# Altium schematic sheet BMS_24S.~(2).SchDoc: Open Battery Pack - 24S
size A3; Date: 26/03/2019; Author: Morgane Vallée - Samuel Lesueur; Revision: 1.0; SheetNumber: 1; SheetTotal: 2
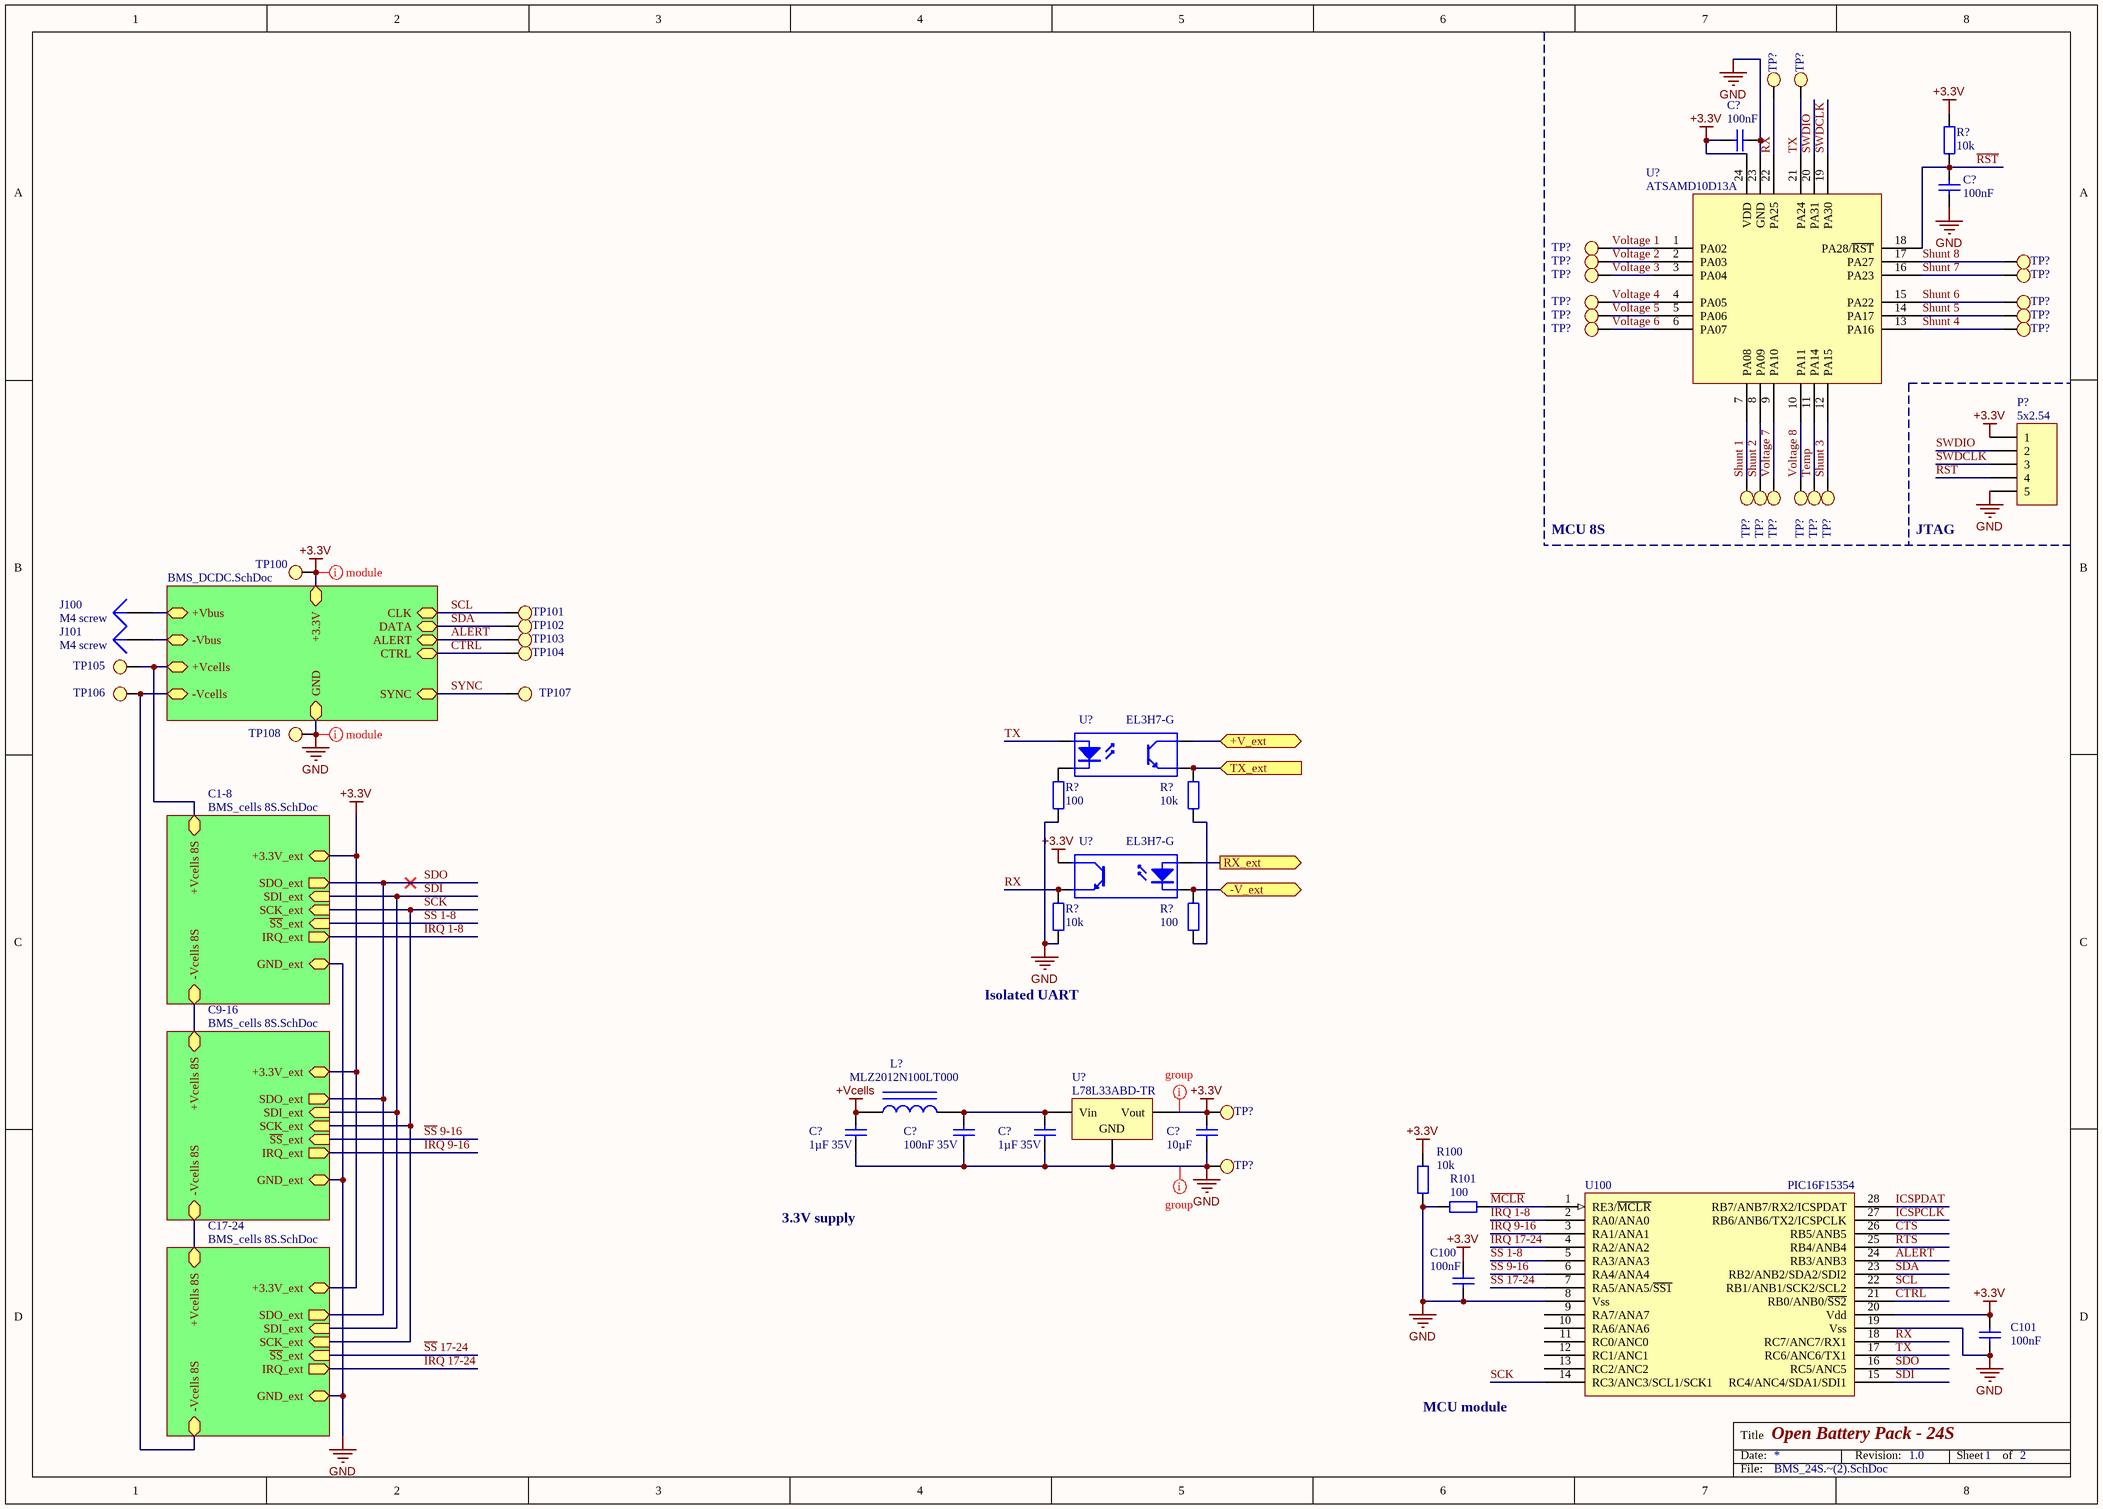
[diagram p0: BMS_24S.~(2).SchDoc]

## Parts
(Parts that share a designator on the sheet are numbered #1, #2 ... from top to bottom, then left to right.)
C100  100nF  [C0603]
C101  100nF  [C0603]
C?#1  100nF  [C0603]
C?#2  100nF  [C0603]
C?#3  1µF 35V  [C0805]
C?#4  100nF 35V  [C0603]
C?#5  1µF 35V  [C0805]
C?#6  10µF  [C0603]
J100  M4 screw  [HOLE_4]
J101  M4 screw  [HOLE_4]
L?  MLZ2012N100LT000  [FER 0805/2012]
P?  5x2.54  [HDR1X5]
R100  10k  [R0603]
R101  100  [R0603]
R?#1  10k  [R0603]
R?#2  10k  [R0603]
R?#3  100  [R0603]
R?#4  100  [R0603]
R?#5  10k  [R0603]
TP100  Test Point  [Test Point]  (value not drawn)
TP101  Test Point  [Test Point]  (value not drawn)
TP102  Test Point  [Test Point]  (value not drawn)
TP103  Test Point  [Test Point]  (value not drawn)
TP104  Test Point  [Test Point]  (value not drawn)
TP105  Test Point  [Test Point]  (value not drawn)
TP106  Test Point  [Test Point]  (value not drawn)
TP107  Test Point  [Test Point]  (value not drawn)
TP108  Test Point  [Test Point]  (value not drawn)
TP?#1  Test Point  [Test Point]  (value not drawn)
TP?#2  Test Point  [Test Point]  (value not drawn)
TP?#3  Test Point  [Test Point]  (value not drawn)
TP?#4  Test Point  [Test Point]  (value not drawn)
TP?#5  Test Point  [Test Point]  (value not drawn)
TP?#6  Test Point  [Test Point]  (value not drawn)
TP?#7  Test Point  [Test Point]  (value not drawn)
TP?#8  Test Point  [Test Point]  (value not drawn)
TP?#9  Test Point  [Test Point]  (value not drawn)
TP?#10  Test Point  [Test Point]  (value not drawn)
TP?#11  Test Point  [Test Point]  (value not drawn)
TP?#12  Test Point  [Test Point]  (value not drawn)
TP?#13  Test Point  [Test Point]  (value not drawn)
TP?#14  Test Point  [Test Point]  (value not drawn)
TP?#15  Test Point  [Test Point]  (value not drawn)
TP?#16  Test Point  [Test Point]  (value not drawn)
TP?#17  Test Point  [Test Point]  (value not drawn)
TP?#18  Test Point  [Test Point]  (value not drawn)
TP?#19  Test Point  [Test Point]  (value not drawn)
TP?#20  Test Point  [Test Point]  (value not drawn)
TP?#21  Test Point  [Test Point]  (value not drawn)
U100  PIC16F15354  [SSOP_28]
U?#1  ATSAMD10D13A  [SMSC QFN-24 4x4MM]
U?#2  EL3H7-G  [OPTO_EL3H7-G]
U?#3  EL3H7-G  [OPTO_EL3H7-G]
U?#4  L78L33ABD-TR  [ST SOIC-8N]

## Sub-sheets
C1-8 = BMS_cells 8S.SchDoc: ~{SS}_ext (in), GND_ext, +3.3V_ext, SCK_ext (in), SDO_ext (out), SDI_ext (in), IRQ_ext (out), -Vcells 8S, +Vcells 8S
C9-16 = BMS_cells 8S.SchDoc: ~{SS}_ext (in), GND_ext, +3.3V_ext, SCK_ext (in), SDO_ext (out), SDI_ext (in), IRQ_ext (out), -Vcells 8S, +Vcells 8S
C17-24 = BMS_cells 8S.SchDoc: ~{SS}_ext (in), GND_ext, +3.3V_ext, SCK_ext (in), SDO_ext (out), SDI_ext (in), IRQ_ext (out), -Vcells 8S, +Vcells 8S
? = BMS_DCDC.SchDoc: CTRL (bidir), SYNC (bidir), CLK (bidir), DATA (bidir), ALERT (bidir), GND, +3.3V, -Vbus, +Vbus, -Vcells, +Vcells

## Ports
+V_ext, -V_ext, RX_ext (out), TX_ext (in)

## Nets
+3.3V: C100.2 C101.2 C?#1.2 C?#6.1 P?.1 R100.2 R?#1.2 TP100.1 TP?#20.1 U100.20(Vdd) U?#1.24(VDD) U?#3.4(C) U?#4.3(Vout) ; sheet /+3.3V, sheet C1-8/+3.3V_ext, sheet C9-16/+3.3V_ext, sheet C17-24/+3.3V_ext
+Vcells: C?#3.1 L?.1
GND: C100.1 C101.1 C?#1.1 C?#2.1 C?#3.2 C?#4.2 C?#5.2 C?#6.2 P?.5 R100.1 R101.2 R?#3.1 R?#5.1 TP108.1 TP?#21.1 U100.8(Vss) U100.19(Vss) U?#1.23(GND) U?#4.2(GND) ; sheet /GND, sheet C1-8/GND_ext, sheet C9-16/GND_ext, sheet C17-24/GND_ext
+V_ext: U?#2.4(C) ; port +V_ext
-V_ext: R?#4.1 U?#3.2(K) ; port -V_ext
ALERT: TP103.1 U100.24(RB3/ANB3) ; sheet /ALERT
CTRL: TP104.1 U100.21(RB0/ANB0/~{SS2}) ; sheet /CTRL
CTS: U100.26(RB5/ANB5)
ICSPCLK: U100.27(RB6/ANB6/TX2/ICSPCLK)
ICSPDAT: U100.28(RB7/ANB7/RX2/ICSPDAT)
IRQ 1-8: U100.2(RA0/ANA0) ; sheet C1-8/IRQ_ext
IRQ 9-16: U100.3(RA1/ANA1) ; sheet C9-16/IRQ_ext
IRQ 17-24: U100.4(RA2/ANA2) ; sheet C17-24/IRQ_ext
~{MCLR}: R101.1 U100.1(RE3/~{MCLR})
~{RST}: C?#2.2 P?.4 R?#1.1 U?#1.18(PA28/~{RST})
RTS: U100.25(RB4/ANB4)
RX: R?#5.2 TP?#1.1 U100.18(RC7/ANC7/RX1) U?#1.22(PA25) U?#3.3(E)
RX_ext: U?#3.1(A) ; port RX_ext
~{SS} 1-8: U100.5(RA3/ANA3) ; sheet C1-8/~{SS}_ext
~{SS} 9-16: U100.6(RA4/ANA4) ; sheet C9-16/~{SS}_ext
~{SS} 17-24: U100.7(RA5/ANA5/~{SS1}) ; sheet C17-24/~{SS}_ext
SCK: U100.14(RC3/ANC3/SCL1/SCK1) ; sheet C1-8/SCK_ext, sheet C9-16/SCK_ext, sheet C17-24/SCK_ext
SCL: TP101.1 U100.22(RB1/ANB1/SCK2/SCL2) ; sheet /CLK
SDA: TP102.1 U100.23(RB2/ANB2/SDA2/SDI2) ; sheet /DATA
SDI: U100.15(RC4/ANC4/SDA1/SDI1) ; sheet C1-8/SDI_ext, sheet C9-16/SDI_ext, sheet C17-24/SDI_ext
SDO: U100.16(RC5/ANC5) ; sheet C1-8/SDO_ext, sheet C9-16/SDO_ext, sheet C17-24/SDO_ext
Shunt 1: TP?#14.1 U?#1.7(PA08)
Shunt 2: TP?#15.1 U?#1.8(PA09)
Shunt 3: TP?#19.1 U?#1.12(PA15)
Shunt 4: TP?#13.1 U?#1.13(PA16)
Shunt 5: TP?#11.1 U?#1.14(PA17)
Shunt 6: TP?#9.1 U?#1.15(PA22)
Shunt 7: TP?#7.1 U?#1.16(PA23)
Shunt 8: TP?#5.1 U?#1.17(PA27)
SWDCLK: P?.3 U?#1.19(PA30)
SWDIO: P?.2 U?#1.20(PA31)
SYNC: TP107.1 ; sheet /SYNC
Temp: TP?#18.1 U?#1.11(PA14)
TX: TP?#2.1 U100.17(RC6/ANC6/TX1) U?#1.21(PA24) U?#2.1(A)
TX_ext: R?#2.1 U?#2.3(E) ; port TX_ext
Voltage 1: TP?#3.1 U?#1.1(PA02)
Voltage 2: TP?#4.1 U?#1.2(PA03)
Voltage 3: TP?#6.1 U?#1.3(PA04)
Voltage 4: TP?#8.1 U?#1.4(PA05)
Voltage 5: TP?#10.1 U?#1.5(PA06)
Voltage 6: TP?#12.1 U?#1.6(PA07)
Voltage 7: TP?#16.1 U?#1.9(PA10)
Voltage 8: TP?#17.1 U?#1.10(PA11)
NetC?#4_1: C?#4.1 C?#5.1 L?.2 U?#4.1(Vin)
NetJ100_1: J100.1 ; sheet /+Vbus
NetJ101_1: J101.1 ; sheet /-Vbus
NetR?#2_2: R?#2.2 R?#4.2
NetR?#3_2: R?#3.2 U?#2.2(K)
NetTP105_1: TP105.1 ; sheet /+Vcells, sheet C1-8/+Vcells 8S
NetTP106_1: TP106.1 ; sheet /-Vcells, sheet C17-24/-Vcells 8S
(unnamed): sheet C1-8/-Vcells 8S, sheet C9-16/+Vcells 8S
(unnamed): sheet C9-16/-Vcells 8S, sheet C17-24/+Vcells 8S  [a separate net that carries the same name]

Not connected (* = marked no-connect by the designer): U100 9(RA7/ANA7) 10(RA6/ANA6) 11(RC0/ANC0) 12(RC1/ANC1) 13(RC2/ANC2)

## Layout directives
net class module: +3.3V, GND
net class Group: +3.3V, GND

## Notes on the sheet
- MCU 8S
- JTAG
- Isolated UART
- 3.3V supply
- MCU module

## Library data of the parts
C100 C101 C?#1-C?#6 = Cap: Capacitor
J100 J101 = Plug
L? = Inductor Iron: Magnetic-Core Inductor
P? = Header 5: Header, 5-Pin
R100 R101 R?#1-R?#5 = Res2: Resistor
U?#2 U?#3 = Optoisolator1: 4-Pin Phototransistor Optocoupler
U?#4 = Volt Reg: Voltage Regulator; pin to pad: 1>8 2>2+3+6+7 3>1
